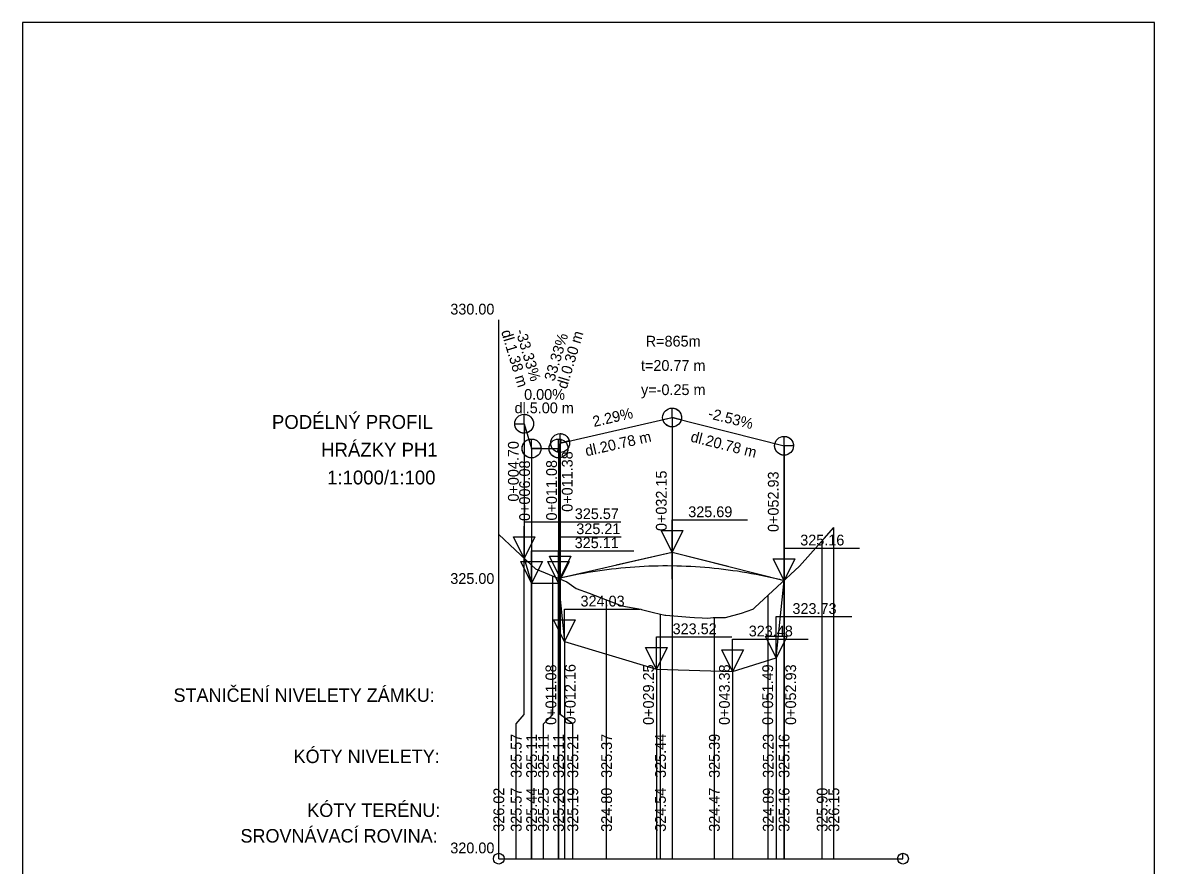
# Model space of a CAD drawing. Extents: x -559854 to -559644, y -1162502 to -1162205.
# Drawn here: x -559854.4 to -559644.4, y -1162360.9 to -1162204.5 of the extents above; entities that cross this region are included whole.
import ezdxf

# ---------------------------------------------------------------- set-up
doc = ezdxf.new("R2010")
doc.units = 0
for name, color, linetype in [('13', 7, 'Continuous'), ('14', 7, 'Continuous'), ('16', 7, 'Continuous'), ('4', 7, 'Continuous'), ('46', 7, 'Continuous'), ('56', 7, 'Continuous'), ('8', 7, 'Continuous'), ('_rám PH2 a PH4', 7, 'Continuous')]:
    doc.layers.add(name, color=color, linetype=linetype)

msp = doc.modelspace()

# ---------------------------------------------------------------- linework, layer by layer
for p, q in [((-559644.4, -1162204.53), (-559854.4, -1162204.53)), ((-559854.4, -1162204.53), (-559854.4, -1162501.53)), ((-559644.4, -1162501.53), (-559644.4, -1162204.53)), ((-559766.04, -1162359.71), (-559766.04, -1162299.51)), ((-559703.87, -1162359.71), (-559703.87, -1162298.21)), ((-559706.04, -1162359.71), (-559706.04, -1162300.71)), ((-559744.27, -1162305.19), (-559733.89, -1162302.82)), ((-559733.89, -1162307.82), (-559733.89, -1162302.82)), ((-559733.89, -1162302.82), (-559723.5, -1162305.44)), ((-559759.96, -1162359.71), (-559759.96, -1162305.31)), ((-559754.96, -1162359.71), (-559754.96, -1162307.71)), ((-559754.66, -1162332.92), (-559754.66, -1162307.81)), ((-559754.66, -1162332.92), (-559754.66, -1162307.81)), ((-559754.96, -1162308.57), (-559753.88, -1162319.4)), ((-559714.55, -1162322.42), (-559713.11, -1162308.07)), ((-559713.11, -1162359.71), (-559713.11, -1162308.11)), ((-559713.11, -1162359.71), (-559713.11, -1162308.11)), ((-559746.04, -1162359.71), (-559746.04, -1162311.71)), ((-559716.04, -1162359.71), (-559716.04, -1162310.81)), ((-559736.04, -1162359.71), (-559736.04, -1162314.31)), ((-559726.04, -1162359.71), (-559726.04, -1162315.01)), ((-559753.88, -1162319.4), (-559736.79, -1162324.54)), ((-559722.66, -1162324.95), (-559714.55, -1162322.42)), ((-559736.79, -1162324.54), (-559722.66, -1162324.95)), ((-559762.81, -1162359.71), (-559762.81, -1162334.68)), ((-559757.77, -1162359.71), (-559757.77, -1162334.68))]:
    msp.add_line(p, q)
for points in [[(-559766.04, -1162299.53), (-559760, -1162305.24), (-559759.25, -1162305.93), (-559753.42, -1162308.34), (-559751.67, -1162309.53), (-559749.3, -1162310.45), (-559743.22, -1162312.75), (-559739.7, -1162313.41), (-559739.56, -1162313.45), (-559737.32, -1162314), (-559735.26, -1162314.48), (-559735.07, -1162314.5), (-559732.82, -1162314.71), (-559730.57, -1162314.87), (-559729.72, -1162314.92), (-559728.32, -1162315.01), (-559727.25, -1162315.07), (-559726.26, -1162314.97), (-559724, -1162314.95), (-559721.01, -1162314.15), (-559718.88, -1162313.4), (-559718.79, -1162313.35), (-559718.51, -1162313.11), (-559710.27, -1162305.41), (-559705.65, -1162300.27), (-559703.87, -1162298.24)], [(-559762.81, -1162334.68), (-559761.34, -1162332.92), (-559761.34, -1162304.01)], [(-559757.77, -1162334.68), (-559756.04, -1162332.92), (-559756.04, -1162307.21)], [(-559752.31, -1162359.71), (-559752.31, -1162334.68), (-559754.66, -1162332.92)]]:
    msp.add_lwpolyline(points)
for centre in [(-559766.04, -1162359.71), (-559691.04, -1162359.71)]:
    msp.add_circle(centre, 1)
at = {"layer": '14'}
for p, q in [((-559754.66, -1162282.57), (-559733.89, -1162277.82)), ((-559733.89, -1162277.82), (-559733.89, -1162359.71)), ((-559733.89, -1162277.82), (-559713.11, -1162283.07)), ((-559761.34, -1162278.98), (-559761.34, -1162278.98)), ((-559761.34, -1162278.98), (-559759.96, -1162283.57)), ((-559754.96, -1162283.57), (-559754.66, -1162282.57)), ((-559754.66, -1162282.57), (-559754.66, -1162332.92)), ((-559759.96, -1162283.57), (-559759.96, -1162359.71)), ((-559759.96, -1162283.57), (-559754.96, -1162283.57)), ((-559754.96, -1162283.57), (-559754.96, -1162359.71)), ((-559713.11, -1162283.07), (-559713.11, -1162359.71)), ((-559754.66, -1162307.57), (-559733.89, -1162302.82)), ((-559733.89, -1162302.82), (-559733.89, -1162359.71)), ((-559733.89, -1162302.82), (-559713.11, -1162308.07)), ((-559761.34, -1162303.98), (-559759.96, -1162308.57)), ((-559761.34, -1162303.98), (-559759.96, -1162308.57)), ((-559761.34, -1162303.98), (-559761.34, -1162303.98)), ((-559761.34, -1162303.98), (-559759.96, -1162308.57)), ((-559754.96, -1162308.57), (-559754.66, -1162307.57)), ((-559754.96, -1162308.57), (-559754.66, -1162307.57)), ((-559754.96, -1162308.57), (-559754.66, -1162307.57)), ((-559754.66, -1162307.57), (-559754.66, -1162307.57)), ((-559754.66, -1162307.57), (-559754.66, -1162307.57)), ((-559754.66, -1162307.57), (-559754.66, -1162332.92)), ((-559759.96, -1162308.57), (-559754.96, -1162308.57)), ((-559759.96, -1162308.57), (-559754.96, -1162308.57)), ((-559759.96, -1162308.57), (-559759.96, -1162359.71)), ((-559759.96, -1162308.57), (-559754.96, -1162308.57)), ((-559754.96, -1162308.57), (-559753.88, -1162319.4)), ((-559754.96, -1162308.57), (-559754.96, -1162359.71)), ((-559754.96, -1162308.57), (-559753.88, -1162319.4)), ((-559754.96, -1162308.57), (-559754.96, -1162308.57)), ((-559754.96, -1162308.57), (-559753.88, -1162319.4)), ((-559714.55, -1162322.42), (-559713.11, -1162308.07)), ((-559714.55, -1162322.42), (-559713.11, -1162308.07)), ((-559714.55, -1162322.42), (-559713.11, -1162308.07)), ((-559713.11, -1162308.07), (-559713.11, -1162308.07)), ((-559713.11, -1162308.07), (-559713.11, -1162308.07)), ((-559713.11, -1162308.07), (-559713.11, -1162359.71)), ((-559713.11, -1162308.07), (-559713.11, -1162359.71)), ((-559753.88, -1162319.4), (-559736.79, -1162324.54)), ((-559753.88, -1162319.4), (-559753.88, -1162359.71)), ((-559753.88, -1162319.4), (-559736.79, -1162324.54)), ((-559722.66, -1162324.95), (-559714.55, -1162322.42)), ((-559722.66, -1162324.95), (-559714.55, -1162322.42)), ((-559714.55, -1162322.42), (-559714.55, -1162359.71)), ((-559736.79, -1162324.54), (-559722.66, -1162324.95)), ((-559736.79, -1162324.54), (-559736.79, -1162359.71)), ((-559736.79, -1162324.54), (-559722.66, -1162324.95)), ((-559722.66, -1162324.95), (-559722.66, -1162359.71))]:
    msp.add_line(p, q, dxfattribs=at)
msp.add_lwpolyline([(-559754.66, -1162307.57), (-559753.8, -1162307.37), (-559752.93, -1162307.19), (-559752.07, -1162307.01), (-559751.2, -1162306.85), (-559750.33, -1162306.69), (-559749.47, -1162306.54), (-559748.6, -1162306.39), (-559747.74, -1162306.26), (-559746.87, -1162306.14), (-559746.01, -1162306.02), (-559745.14, -1162305.92), (-559744.27, -1162305.82), (-559743.41, -1162305.73), (-559742.54, -1162305.65), (-559741.68, -1162305.58), (-559740.81, -1162305.51), (-559739.95, -1162305.46), (-559739.08, -1162305.41), (-559738.22, -1162305.37), (-559737.35, -1162305.35), (-559736.48, -1162305.33), (-559735.62, -1162305.31), (-559734.75, -1162305.31), (-559733.02, -1162305.33), (-559732.16, -1162305.36), (-559731.29, -1162305.39), (-559730.42, -1162305.43), (-559729.56, -1162305.48), (-559728.69, -1162305.54), (-559727.83, -1162305.6), (-559726.96, -1162305.68), (-559726.1, -1162305.76), (-559725.23, -1162305.86), (-559724.37, -1162305.96), (-559723.5, -1162306.07), (-559722.63, -1162306.19), (-559721.77, -1162306.31), (-559720.9, -1162306.45), (-559720.04, -1162306.6), (-559719.17, -1162306.75), (-559718.31, -1162306.91), (-559717.44, -1162307.08), (-559716.57, -1162307.26), (-559715.71, -1162307.45), (-559714.84, -1162307.65), (-559713.98, -1162307.85), (-559713.11, -1162308.07)], dxfattribs=at)
at = {"layer": '16'}
msp.add_lwpolyline([(-559754.66, -1162307.57), (-559753.8, -1162307.37), (-559752.93, -1162307.19), (-559752.07, -1162307.01), (-559751.2, -1162306.85), (-559750.33, -1162306.69), (-559749.47, -1162306.54), (-559748.6, -1162306.39), (-559747.74, -1162306.26), (-559746.87, -1162306.14), (-559746.01, -1162306.02), (-559745.14, -1162305.92), (-559744.27, -1162305.82), (-559743.41, -1162305.73), (-559742.54, -1162305.65), (-559741.68, -1162305.58), (-559740.81, -1162305.51), (-559739.95, -1162305.46), (-559739.08, -1162305.41), (-559738.22, -1162305.37), (-559737.35, -1162305.35), (-559736.48, -1162305.33), (-559735.62, -1162305.31), (-559734.75, -1162305.31), (-559733.02, -1162305.33), (-559732.16, -1162305.36), (-559731.29, -1162305.39), (-559730.42, -1162305.43), (-559729.56, -1162305.48), (-559728.69, -1162305.54), (-559727.83, -1162305.6), (-559726.96, -1162305.68), (-559726.1, -1162305.76), (-559725.23, -1162305.86), (-559724.37, -1162305.96), (-559723.5, -1162306.07), (-559722.63, -1162306.19), (-559721.77, -1162306.31), (-559720.9, -1162306.45), (-559720.04, -1162306.6), (-559719.17, -1162306.75), (-559718.31, -1162306.91), (-559717.44, -1162307.08), (-559716.57, -1162307.26), (-559715.71, -1162307.45), (-559714.84, -1162307.65), (-559713.98, -1162307.85), (-559713.11, -1162308.07)], dxfattribs=at)
at = {"layer": '46'}
for points in [[(-559733.89, -1162277.82), (-559733.89, -1162276.07), (-559733.78, -1162276.07), (-559733.66, -1162276.08), (-559733.55, -1162276.1), (-559733.44, -1162276.12), (-559733.34, -1162276.16), (-559733.23, -1162276.2), (-559733.13, -1162276.24), (-559733.03, -1162276.29), (-559732.93, -1162276.35), (-559732.84, -1162276.41), (-559732.75, -1162276.48), (-559732.67, -1162276.56), (-559732.59, -1162276.64), (-559732.52, -1162276.73), (-559732.45, -1162276.82), (-559732.39, -1162276.91), (-559732.34, -1162277.01), (-559732.29, -1162277.11), (-559732.25, -1162277.21), (-559732.21, -1162277.32), (-559732.18, -1162277.43), (-559732.16, -1162277.54), (-559732.15, -1162277.65), (-559732.14, -1162277.76), (-559732.14, -1162277.87), (-559732.15, -1162277.99), (-559732.16, -1162278.1), (-559732.18, -1162278.21), (-559732.19, -1162278.25), (-559733.89, -1162277.82), (-559733.89, -1162279.57), (-559734, -1162279.56), (-559734.11, -1162279.55), (-559734.22, -1162279.54), (-559734.33, -1162279.51), (-559734.44, -1162279.48), (-559734.54, -1162279.44), (-559734.65, -1162279.39), (-559734.75, -1162279.34), (-559734.84, -1162279.28), (-559734.93, -1162279.22), (-559735.02, -1162279.15), (-559735.1, -1162279.07), (-559735.18, -1162278.99), (-559735.26, -1162278.91), (-559735.32, -1162278.82), (-559735.38, -1162278.72), (-559735.44, -1162278.63), (-559735.49, -1162278.53), (-559735.53, -1162278.42), (-559735.57, -1162278.32), (-559735.59, -1162278.21)], [(-559761.34, -1162278.98), (-559761.34, -1162277.23), (-559761.23, -1162277.23), (-559761.12, -1162277.25), (-559761.01, -1162277.26), (-559760.9, -1162277.29), (-559760.79, -1162277.32), (-559760.68, -1162277.36), (-559760.58, -1162277.4), (-559760.48, -1162277.46), (-559760.39, -1162277.51), (-559760.29, -1162277.58), (-559760.21, -1162277.65), (-559760.12, -1162277.72), (-559760.04, -1162277.8), (-559759.97, -1162277.89), (-559759.9, -1162277.98), (-559759.84, -1162278.07), (-559759.79, -1162278.17), (-559759.74, -1162278.27), (-559759.7, -1162278.38), (-559759.66, -1162278.48), (-559759.63, -1162278.59), (-559759.61, -1162278.7), (-559759.6, -1162278.81), (-559759.59, -1162278.92), (-559759.59, -1162279.04), (-559759.6, -1162279.15), (-559759.61, -1162279.26), (-559759.63, -1162279.37), (-559759.66, -1162279.48), (-559759.7, -1162279.59), (-559759.74, -1162279.69), (-559759.79, -1162279.79), (-559759.84, -1162279.89), (-559759.9, -1162279.98), (-559759.97, -1162280.07), (-559760.04, -1162280.16), (-559760.12, -1162280.24), (-559760.21, -1162280.31), (-559760.29, -1162280.38), (-559760.39, -1162280.45), (-559760.48, -1162280.51), (-559760.58, -1162280.56), (-559760.68, -1162280.6), (-559760.79, -1162280.64), (-559760.84, -1162280.66), (-559761.34, -1162278.98), (-559761.34, -1162280.73), (-559761.45, -1162280.73), (-559761.56, -1162280.72), (-559761.67, -1162280.7), (-559761.78, -1162280.67), (-559761.89, -1162280.64), (-559762, -1162280.6), (-559762.1, -1162280.56), (-559762.2, -1162280.51), (-559762.29, -1162280.45), (-559762.39, -1162280.38), (-559762.47, -1162280.31), (-559762.56, -1162280.24), (-559762.64, -1162280.16), (-559762.71, -1162280.07), (-559762.78, -1162279.98), (-559762.84, -1162279.89), (-559762.89, -1162279.79), (-559762.94, -1162279.69), (-559762.98, -1162279.59), (-559763.02, -1162279.48), (-559763.05, -1162279.37), (-559763.07, -1162279.26), (-559763.08, -1162279.15), (-559763.09, -1162279.04), (-559763.09, -1162278.98)], [(-559759.96, -1162283.57), (-559759.96, -1162281.82), (-559759.85, -1162281.82), (-559759.74, -1162281.83), (-559759.63, -1162281.85), (-559759.52, -1162281.87), (-559759.41, -1162281.91), (-559759.31, -1162281.95), (-559759.2, -1162281.99), (-559759.11, -1162282.04), (-559759.01, -1162282.1), (-559758.92, -1162282.17), (-559758.83, -1162282.24), (-559758.75, -1162282.31), (-559758.67, -1162282.39), (-559758.6, -1162282.48), (-559758.53, -1162282.57), (-559758.47, -1162282.66), (-559758.41, -1162282.76), (-559758.36, -1162282.86), (-559758.32, -1162282.96), (-559758.29, -1162283.07), (-559758.26, -1162283.18), (-559758.24, -1162283.29), (-559758.22, -1162283.4), (-559758.22, -1162283.51), (-559758.21, -1162283.57), (-559759.96, -1162283.57), (-559759.96, -1162285.32), (-559760.08, -1162285.31), (-559760.19, -1162285.3), (-559760.3, -1162285.29), (-559760.41, -1162285.26), (-559760.52, -1162285.23), (-559760.62, -1162285.19), (-559760.72, -1162285.14), (-559760.82, -1162285.09), (-559760.92, -1162285.03), (-559761.01, -1162284.97), (-559761.1, -1162284.9), (-559761.18, -1162284.82), (-559761.26, -1162284.74), (-559761.33, -1162284.66), (-559761.4, -1162284.57), (-559761.46, -1162284.47), (-559761.52, -1162284.38), (-559761.56, -1162284.28), (-559761.61, -1162284.17), (-559761.64, -1162284.07), (-559761.67, -1162283.96), (-559761.69, -1162283.85), (-559761.71, -1162283.74), (-559761.71, -1162283.62), (-559761.71, -1162283.51), (-559761.71, -1162283.4), (-559761.69, -1162283.29), (-559761.67, -1162283.18), (-559761.64, -1162283.07), (-559761.61, -1162282.96), (-559761.56, -1162282.86), (-559761.52, -1162282.76), (-559761.46, -1162282.66), (-559761.4, -1162282.57), (-559761.33, -1162282.48), (-559761.26, -1162282.39), (-559761.18, -1162282.31), (-559761.1, -1162282.24), (-559761.01, -1162282.17), (-559760.92, -1162282.1), (-559760.82, -1162282.04), (-559760.72, -1162281.99), (-559760.62, -1162281.95), (-559760.52, -1162281.91), (-559760.47, -1162281.89)], [(-559754.96, -1162283.57), (-559754.96, -1162281.82), (-559754.85, -1162281.82), (-559754.74, -1162281.83), (-559754.63, -1162281.85), (-559754.52, -1162281.87), (-559754.46, -1162281.89), (-559754.96, -1162283.57), (-559754.96, -1162285.32), (-559755.08, -1162285.31), (-559755.19, -1162285.3), (-559755.3, -1162285.29), (-559755.41, -1162285.26), (-559755.52, -1162285.23), (-559755.62, -1162285.19), (-559755.72, -1162285.14), (-559755.82, -1162285.09), (-559755.92, -1162285.03), (-559756.01, -1162284.97), (-559756.1, -1162284.9), (-559756.18, -1162284.82), (-559756.26, -1162284.74), (-559756.33, -1162284.66), (-559756.4, -1162284.57), (-559756.46, -1162284.47), (-559756.52, -1162284.38), (-559756.56, -1162284.28), (-559756.61, -1162284.17), (-559756.64, -1162284.07), (-559756.67, -1162283.96), (-559756.69, -1162283.85), (-559756.71, -1162283.74), (-559756.71, -1162283.62), (-559756.71, -1162283.57)], [(-559754.66, -1162282.57), (-559754.66, -1162280.82), (-559754.55, -1162280.82), (-559754.44, -1162280.83), (-559754.33, -1162280.85), (-559754.22, -1162280.87), (-559754.11, -1162280.91), (-559754.01, -1162280.95), (-559753.9, -1162280.99), (-559753.81, -1162281.04), (-559753.71, -1162281.1), (-559753.62, -1162281.17), (-559753.53, -1162281.24), (-559753.45, -1162281.31), (-559753.37, -1162281.39), (-559753.3, -1162281.48), (-559753.23, -1162281.57), (-559753.17, -1162281.66), (-559753.11, -1162281.76), (-559753.06, -1162281.86), (-559753.02, -1162281.96), (-559752.99, -1162282.07), (-559752.96, -1162282.18), (-559754.66, -1162282.57), (-559754.66, -1162284.32), (-559754.78, -1162284.31), (-559754.89, -1162284.3), (-559755, -1162284.29), (-559755.11, -1162284.26), (-559755.17, -1162284.24)], [(-559713.11, -1162283.07), (-559713.11, -1162281.32), (-559713, -1162281.32), (-559712.89, -1162281.33), (-559712.78, -1162281.35), (-559712.67, -1162281.37), (-559712.56, -1162281.41), (-559712.45, -1162281.45), (-559712.35, -1162281.49), (-559712.25, -1162281.54), (-559712.16, -1162281.6), (-559712.06, -1162281.67), (-559711.98, -1162281.74), (-559711.89, -1162281.81), (-559711.81, -1162281.89), (-559711.74, -1162281.98), (-559711.68, -1162282.07), (-559711.61, -1162282.16), (-559711.56, -1162282.26), (-559711.51, -1162282.36), (-559711.47, -1162282.46), (-559711.43, -1162282.57), (-559711.4, -1162282.68), (-559711.38, -1162282.79), (-559711.37, -1162282.9), (-559711.36, -1162283.01), (-559711.36, -1162283.07), (-559713.11, -1162283.07), (-559713.11, -1162284.82), (-559713.22, -1162284.81), (-559713.33, -1162284.8), (-559713.44, -1162284.79), (-559713.55, -1162284.76), (-559713.66, -1162284.73), (-559713.77, -1162284.69), (-559713.87, -1162284.64), (-559713.97, -1162284.59), (-559714.07, -1162284.53), (-559714.16, -1162284.47), (-559714.24, -1162284.4), (-559714.33, -1162284.32), (-559714.41, -1162284.24), (-559714.48, -1162284.16), (-559714.55, -1162284.07), (-559714.61, -1162283.97), (-559714.66, -1162283.88), (-559714.71, -1162283.78), (-559714.75, -1162283.67), (-559714.79, -1162283.57), (-559714.82, -1162283.46), (-559714.84, -1162283.35), (-559714.85, -1162283.24), (-559714.86, -1162283.12), (-559714.86, -1162283.01), (-559714.85, -1162282.9), (-559714.84, -1162282.79), (-559714.82, -1162282.68), (-559714.81, -1162282.64)], [(-559733.89, -1162302.82), (-559735.89, -1162298.82), (-559731.89, -1162298.82)], [(-559761.34, -1162303.98), (-559763.34, -1162299.98), (-559759.34, -1162299.98)], [(-559754.66, -1162307.57), (-559756.66, -1162303.57), (-559752.66, -1162303.57)], [(-559759.96, -1162308.57), (-559761.96, -1162304.57), (-559757.96, -1162304.57)], [(-559754.96, -1162308.57), (-559756.96, -1162304.57), (-559752.96, -1162304.57)], [(-559754.96, -1162308.57), (-559756.96, -1162304.57), (-559752.96, -1162304.57)], [(-559713.11, -1162308.07), (-559715.11, -1162304.07), (-559711.11, -1162304.07)], [(-559713.11, -1162308.07), (-559715.11, -1162304.07), (-559711.11, -1162304.07)], [(-559753.88, -1162319.4), (-559755.88, -1162315.4), (-559751.88, -1162315.4)], [(-559714.55, -1162322.42), (-559716.55, -1162318.42), (-559712.55, -1162318.42)], [(-559736.79, -1162324.54), (-559738.79, -1162320.54), (-559734.79, -1162320.54)], [(-559722.66, -1162324.95), (-559724.66, -1162320.95), (-559720.66, -1162320.95)]]:
    msp.add_lwpolyline(points, close=True, dxfattribs=at)
for centre in [(-559733.89, -1162277.82), (-559761.34, -1162278.98), (-559759.96, -1162283.57), (-559754.96, -1162283.57), (-559754.66, -1162282.57), (-559713.11, -1162283.07)]:
    msp.add_circle(centre, 1.75, dxfattribs=at)
at = {"layer": '56'}
for p, q in [((-559766.04, -1162359.71), (-559766.04, -1162259.71)), ((-559766.04, -1162359.71), (-559766.04, -1162358.71)), ((-559766.04, -1162359.71), (-559691.04, -1162359.71)), ((-559691.04, -1162359.71), (-559691.04, -1162358.71))]:
    msp.add_line(p, q, dxfattribs=at)
at = {"layer": '8'}
for p, q in [((-559754.66, -1162307.57), (-559754.66, -1162282.57)), ((-559713.11, -1162308.07), (-559713.11, -1162283.07)), ((-559761.34, -1162297.18), (-559743.42, -1162297.18)), ((-559733.89, -1162302.82), (-559733.89, -1162296.82)), ((-559733.89, -1162296.82), (-559719.89, -1162296.82)), ((-559761.34, -1162303.98), (-559761.34, -1162297.98)), ((-559754.66, -1162299.97), (-559743.33, -1162299.97)), ((-559754.66, -1162307.57), (-559754.66, -1162301.57)), ((-559759.96, -1162308.57), (-559759.96, -1162302.57)), ((-559759.96, -1162302.57), (-559743.58, -1162302.57)), ((-559754.96, -1162308.57), (-559754.96, -1162302.57)), ((-559754.96, -1162302.57), (-559740.96, -1162302.57)), ((-559754.96, -1162308.57), (-559754.96, -1162302.57)), ((-559713.11, -1162308.07), (-559713.11, -1162302.07)), ((-559713.11, -1162302.07), (-559699.11, -1162302.07)), ((-559713.11, -1162308.07), (-559713.11, -1162302.07)), ((-559713.11, -1162302.07), (-559699.11, -1162302.07)), ((-559753.88, -1162319.4), (-559753.88, -1162313.4)), ((-559753.88, -1162313.4), (-559739.88, -1162313.4)), ((-559714.55, -1162322.42), (-559714.55, -1162314.78)), ((-559714.55, -1162314.78), (-559700.55, -1162314.78)), ((-559736.79, -1162324.54), (-559736.79, -1162318.54)), ((-559736.79, -1162318.54), (-559722.79, -1162318.54)), ((-559722.66, -1162324.95), (-559722.66, -1162318.95)), ((-559722.66, -1162318.95), (-559708.66, -1162318.95))]:
    msp.add_line(p, q, dxfattribs=at)
at = {"layer": '_rám PH2 a PH4'}
msp.add_line((-559761.34, -1162278.98), (-559761.34, -1162304.01), dxfattribs=at)

# ---------------------------------------------------------------- texts
for s, p in [('STANIČENÍ NIVELETY ZÁMKU:', (-559826.4, -1162330.6)), (' KÓTY NIVELETY:', (-559805.05, -1162341.96)), (' KÓTY TERÉNU:', (-559802.52, -1162351.96))]:
    msp.add_text(s, height=2.5).set_placement(p)
for s, p in [('325.57', (-559761.81, -1162344.71)), ('325.11', (-559758.96, -1162344.71)), ('325.11', (-559756.77, -1162344.71)), ('325.11', (-559753.96, -1162344.71)), ('325.21', (-559751.31, -1162344.71)), ('325.37', (-559745.04, -1162344.71)), ('325.44', (-559735.04, -1162344.71)), ('325.39', (-559725.04, -1162344.71)), ('325.23', (-559715.04, -1162344.71)), ('325.16', (-559712.11, -1162344.71)), ('325.16', (-559712.11, -1162344.71)), ('326.02', (-559765.04, -1162354.71)), ('325.57', (-559761.81, -1162354.71)), ('325.44', (-559758.96, -1162354.71)), ('325.25', (-559756.77, -1162354.71)), ('325.20', (-559753.96, -1162354.71)), ('325.19', (-559751.31, -1162354.71)), ('324.80', (-559745.04, -1162354.71)), ('324.54', (-559735.04, -1162354.71)), ('324.47', (-559725.04, -1162354.71)), ('324.89', (-559715.04, -1162354.71)), ('325.16', (-559712.11, -1162354.71)), ('325.16', (-559712.11, -1162354.71)), ('325.90', (-559705.04, -1162354.71)), ('326.15', (-559702.87, -1162354.71))]:
    msp.add_text(s, height=2, rotation=90).set_placement(p)
at = {"layer": '13'}
for s, height, p in [('330.00', 2, (-559775.04, -1162258.71)), ('330.00', 2, (-559775.04, -1162258.71)), ('325.00', 2, (-559775.04, -1162308.71)), ('SROVNÁVACÍ ROVINA:', 2.5, (-559813.98, -1162356.71)), ('320.00', 2, (-559775.04, -1162358.71))]:
    msp.add_text(s, height=height, dxfattribs=at).set_placement(p)
at = {"layer": '16'}
for s, rotation, p in [('dl.1.38 m', 286.6992, (-559765.63, -1162261.86)), ('-33.33%', 286.6992, (-559762.97, -1162261.75)), ('33.33%', 73.3008, (-559755.75, -1162271.21)), ('dl.0.30 m', 73.3008, (-559753.46, -1162272.65)), ('2.29%', 12.8786, (-559748.39, -1162279.59)), ('-2.53%', 345.8181, (-559727.34, -1162277.93)), ('dl.20.78 m', 345.8181, (-559730.59, -1162282.26)), ('0+004.70', 90, (-559762.34, -1162293.43)), ('dl.20.78 m', 12.8786, (-559749.77, -1162285.04)), ('0+011.38', 90, (-559752.34, -1162295.33)), ('0+006.08', 90, (-559760.25, -1162297.03)), ('0+011.08', 90, (-559755.25, -1162296.94)), ('0+032.15', 90, (-559734.89, -1162298.9)), ('0+052.93', 90, (-559714.11, -1162299.07)), ('0+011.08', 90, (-559755.37, -1162334.88)), ('0+012.16', 90, (-559751.79, -1162334.81)), ('0+029.25', 90, (-559737.27, -1162334.88)), ('0+043.38', 90, (-559723.18, -1162334.88)), ('0+051.49', 90, (-559715.15, -1162334.88)), ('0+052.93', 90, (-559710.88, -1162334.88))]:
    msp.add_text(s, height=2, rotation=rotation, dxfattribs=at).set_placement(p)
for s, p in [('R=865m', (-559738.78, -1162264.66)), ('t=20.77 m', (-559739.66, -1162269.16)), ('y=-0.25 m', (-559739.65, -1162273.66)), ('0.00%', (-559761.34, -1162274.54)), ('dl.5.00 m', (-559763.12, -1162277.03)), ('325.57', (-559751.94, -1162296.68)), ('325.69', (-559730.89, -1162296.32)), ('325.21', (-559751.66, -1162299.47)), ('325.16', (-559710.11, -1162301.57)), ('325.11', (-559751.96, -1162302.07)), ('325.11', (-559751.96, -1162302.07)), ('324.03', (-559750.88, -1162312.9)), ('323.73', (-559711.55, -1162314.28)), ('323.52', (-559733.79, -1162318.04)), ('323.48', (-559719.66, -1162318.45))]:
    msp.add_text(s, height=2, dxfattribs=at).set_placement(p)
at = {"layer": '4'}
for s, height, p in [('PODÉLNÝ PROFIL ', 2.5762, (-559808.14, -1162279.94)), ('HRÁZKY PH1', 2.576, (-559799.01, -1162285.09)), ('1:1000/1:100', 2.5762, (-559797.9, -1162290.24))]:
    msp.add_text(s, height=height, dxfattribs=at).set_placement(p)

doc.saveas('drawing.dxf')
